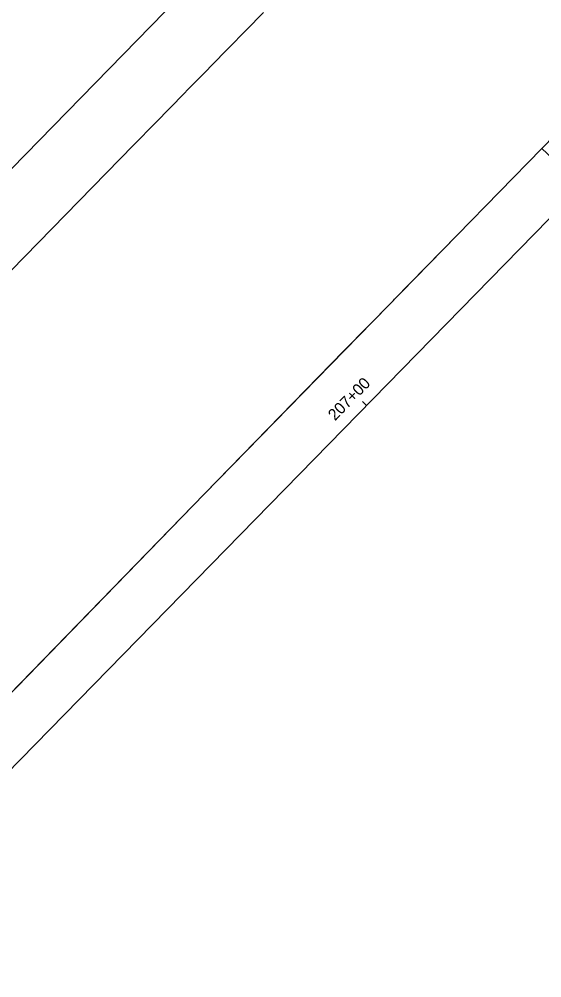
# Model space of a CAD drawing. Extents: x 2251012 to 2259557, y 13786786 to 13792525.
# Drawn here: x 2253138.2 to 2253219.9, y 13788849.4 to 13788999.2 of the extents above; entities that cross this region are included whole.
import ezdxf

# ---------------------------------------------------------------- set-up
doc = ezdxf.new("R2010")
doc.units = 0
for name, color, linetype in [('D_ALIGN_ANNO_1', 7, 'Continuous'), ('D_BOXES_1', 7, 'Continuous'), ('D_DRN_AREA_X', 7, 'Continuous'), ('Grade_DitchLine', 7, 'Continuous')]:
    doc.layers.add(name, color=color, linetype=linetype)

msp = doc.modelspace()

# ---------------------------------------------------------------- linework, layer by layer
at = {"layer": 'D_ALIGN_ANNO_1'}
msp.add_line((2253192.48, 13788938.83), (2253191.84, 13788939.46), dxfattribs=at)
at = {"layer": 'D_BOXES_1'}
msp.add_line((2253067.97, 13788905.31), (2253422.35, 13789267.76), dxfattribs=at)
at = {"layer": 'D_DRN_AREA_X'}
for p, q in [((2253168.2, 13788991.97), (2253176.35, 13789000.31)), ((2253176.35, 13789000.31), (2253168.2, 13788991.97)), ((2253219.88, 13788979.03), (2253238.61, 13788998.19)), ((2253166.52, 13788990.25), (2253167.25, 13788990.99)), ((2253167.25, 13788990.99), (2253166.52, 13788990.25)), ((2253167.25, 13788990.99), (2253167.34, 13788991.08)), ((2253167.34, 13788991.08), (2253167.25, 13788990.99)), ((2253167.44, 13788991.19), (2253167.34, 13788991.08)), ((2253168.2, 13788991.97), (2253167.44, 13788991.19)), ((2253164.55, 13788988.23), (2253166.52, 13788990.25)), ((2253166.52, 13788990.25), (2253164.55, 13788988.23)), ((2253163.95, 13788987.62), (2253164.55, 13788988.23)), ((2253164.55, 13788988.23), (2253163.95, 13788987.62)), ((2253159.54, 13788983.11), (2253163.95, 13788987.62)), ((2253163.95, 13788987.62), (2253159.54, 13788983.11)), ((2253156.05, 13788979.53), (2253159.54, 13788983.11)), ((2253159.54, 13788983.11), (2253156.05, 13788979.53)), ((2253121.48, 13788944.16), (2253156.05, 13788979.53)), ((2253156.05, 13788979.53), (2253121.48, 13788944.16)), ((2253219.88, 13788979.03), (2253343.04, 13788861.89)), ((2253343.04, 13788861.89), (2253219.88, 13788979.03)), ((2253188.94, 13788947.38), (2253196.67, 13788955.28)), ((2253196.67, 13788955.28), (2253196.84, 13788955.46)), ((2253167.13, 13788925.05), (2253188.94, 13788947.38)), ((2253127.32, 13788884.07), (2253167.13, 13788925.05))]:
    msp.add_line(p, q, dxfattribs=at)
for points in [[(2253498.79, 13789264.43), (2253238.61, 13788998.19), (2253219.88, 13788979.03)], [(2253167.34, 13788991.08), (2253167.44, 13788991.19), (2253168.2, 13788991.97)], [(2253219.88, 13788979.03), (2253206.62, 13788965.47), (2253167.13, 13788925.05), (2253127.32, 13788884.07), (2253097.55, 13788852.82), (2253095.25, 13788850.52), (2253094.09, 13788849.37)], [(2253196.84, 13788955.46), (2253206.62, 13788965.47), (2253219.88, 13788979.03)]]:
    msp.add_lwpolyline(points, dxfattribs=at)
at = {"layer": 'Grade_DitchLine'}
msp.add_line((2253223.25, 13788970.32), (2253136.1, 13788881.14), dxfattribs=at)

# ---------------------------------------------------------------- texts
at = {"layer": 'D_ALIGN_ANNO_1'}
msp.add_text('207+00', height=1.8, rotation=45.6588, dxfattribs=at).set_placement((2253187.55, 13788936.37))

doc.saveas('drawing.dxf')
